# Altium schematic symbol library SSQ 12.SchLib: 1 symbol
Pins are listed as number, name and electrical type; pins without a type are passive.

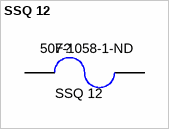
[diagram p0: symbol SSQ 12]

## SSQ 12
designator F?  Supplier Part Number: 507-1058-1-ND
FUSE BOARD MNT 12A 125VAC 86VDC; Manufacturer: Bel Fuse Inc; U/M: EA; Response Time: Fast; Fuse Type: Board Mount (Cartridge Style Excluded); Voltage Rating - DC: 86V; Approvals: CE, cULus; DC Cold Resistance: 0.005 Ohm; Voltage Rating - AC: 125V; Melting I²t: 70; Breaking Capacity @ Rated Voltage: 50A AC, 10kA DC
simulation model Fuse (Altium default FUSE subcircuit)
footprint SSQ (BEL FUSE INC SSQ FUSE)
pins: 1, 2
